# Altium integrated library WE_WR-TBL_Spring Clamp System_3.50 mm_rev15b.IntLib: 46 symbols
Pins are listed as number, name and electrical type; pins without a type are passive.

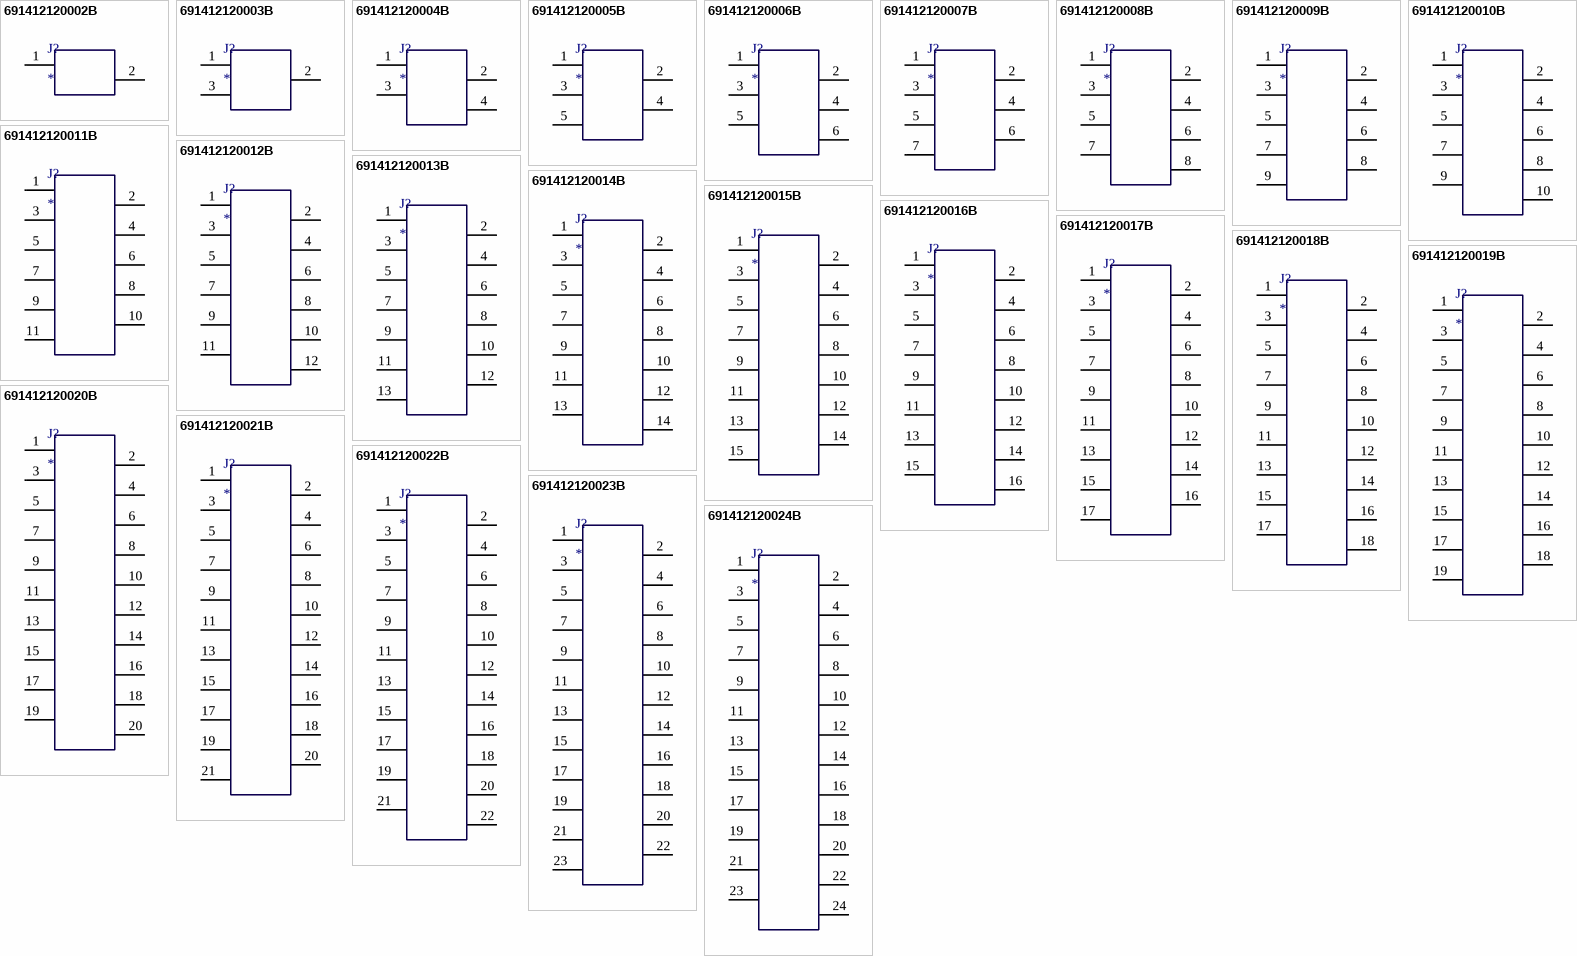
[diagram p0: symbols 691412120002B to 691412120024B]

## 691412120002B
designator J?
WR-TBL Screwless Entry 45° Grey,Serie 412 B - 3.50 mm; Manufacturer: Würth Elektronik eiSos GmbH; partNo: 691412120002B; ComponentLink1 Description: Manufacturer; ComponentLink2 Description: Datasheet; NoPins: 2
footprint 691412120002B
pins: 1, 2

## 691412120003B
designator J?
WR-TBL Screwless Entry 45° Grey,Serie 412 B - 3.50 mm; Manufacturer: Würth Elektronik eiSos GmbH; partNo: 691412120003B; ComponentLink1 Description: Manufacturer; ComponentLink2 Description: Datasheet; NoPins: 3
footprint 691412120003B
pins: 1, 2, 3

## 691412120004B
designator J?
WR-TBL Screwless Entry 45° Grey,Serie 412 B - 3.50 mm; Manufacturer: Würth Elektronik eiSos GmbH; partNo: 691412120004B; ComponentLink1 Description: Manufacturer; ComponentLink2 Description: Datasheet; NoPins: 4
footprint 691412120004B
pins: 1, 2, 3, 4

## 691412120005B
designator J?
WR-TBL Screwless Entry 45° Grey,Serie 412 B - 3.50 mm; Manufacturer: Würth Elektronik eiSos GmbH; partNo: 691412120005B; ComponentLink1 Description: Manufacturer; ComponentLink2 Description: Datasheet; NoPins: 5
footprint 691412120005B
pins: 1, 2, 3, 4, 5

## 691412120006B
designator J?
WR-TBL Screwless Entry 45° Grey,Serie 412 B - 3.50 mm; Manufacturer: Würth Elektronik eiSos GmbH; partNo: 691412120006B; ComponentLink1 Description: Manufacturer; ComponentLink2 Description: Datasheet; NoPins: 6
footprint 691412120006B
pins: 1, 2, 3, 4, 5, 6

## 691412120007B
designator J?
WR-TBL Screwless Entry 45° Grey,Serie 412 B - 3.50 mm; Manufacturer: Würth Elektronik eiSos GmbH; partNo: 691412120007B; ComponentLink1 Description: Manufacturer; ComponentLink2 Description: Datasheet; NoPins: 7
footprint 691412120007B
pins: 1, 2, 3, 4, 5, 6, 7

## 691412120008B
designator J?
WR-TBL Screwless Entry 45° Grey,Serie 412 B - 3.50 mm; Manufacturer: Würth Elektronik eiSos GmbH; partNo: 691412120008B; ComponentLink1 Description: Manufacturer; ComponentLink2 Description: Datasheet; NoPins: 8
footprint 691412120008B
pins: 1, 2, 3, 4, 5, 6, 7, 8

## 691412120009B
designator J?
WR-TBL Screwless Entry 45° Grey,Serie 412 B - 3.50 mm; Manufacturer: Würth Elektronik eiSos GmbH; partNo: 691412120009B; ComponentLink1 Description: Manufacturer; ComponentLink2 Description: Datasheet; NoPins: 9
footprint 691412120009B
pins: 1, 2, 3, 4, 5, 6, 7, 8, 9

## 691412120010B
designator J?
WR-TBL Screwless Entry 45° Grey,Serie 412 B - 3.50 mm; Manufacturer: Würth Elektronik eiSos GmbH; partNo: 691412120010B; ComponentLink1 Description: Manufacturer; ComponentLink2 Description: Datasheet; NoPins: 10
footprint 691412120010B
pins: 1, 2, 3, 4, 5, 6, 7, 8, 9, 10

## 691412120011B
designator J?
WR-TBL Screwless Entry 45° Grey,Serie 412 B - 3.50 mm; Manufacturer: Würth Elektronik eiSos GmbH; partNo: 691412120011B; ComponentLink1 Description: Manufacturer; ComponentLink2 Description: Datasheet; NoPins: 11
footprint 691412120011B
pins: 1, 2, 3, 4, 5, 6, 7, 8, 9, 10, 11

## 691412120012B
designator J?
WR-TBL Screwless Entry 45° Grey,Serie 412 B - 3.50 mm; Manufacturer: Würth Elektronik eiSos GmbH; partNo: 691412120012B; ComponentLink1 Description: Manufacturer; ComponentLink2 Description: Datasheet; NoPins: 12
footprint 691412120012B
pins: 1, 2, 3, 4, 5, 6, 7, 8, 9, 10, 11, 12

## 691412120013B
designator J?
WR-TBL Screwless Entry 45° Grey,Serie 412 B - 3.50 mm; Manufacturer: Würth Elektronik eiSos GmbH; partNo: 691412120013B; ComponentLink1 Description: Manufacturer; ComponentLink2 Description: Datasheet; NoPins: 13
footprint 691412120013B
pins: 1, 2, 3, 4, 5, 6, 7, 8, 9, 10, 11, 12, 13

## 691412120014B
designator J?
WR-TBL Screwless Entry 45° Grey,Serie 412 B - 3.50 mm; Manufacturer: Würth Elektronik eiSos GmbH; partNo: 691412120014B; ComponentLink1 Description: Manufacturer; ComponentLink2 Description: Datasheet; NoPins: 14
footprint 691412120014B
pins: 1, 2, 3, 4, 5, 6, 7, 8, 9, 10, 11, 12, 13, 14

## 691412120015B
designator J?
WR-TBL Screwless Entry 45° Grey,Serie 412 B - 3.50 mm; Manufacturer: Würth Elektronik eiSos GmbH; partNo: 691412120015B; ComponentLink1 Description: Manufacturer; ComponentLink2 Description: Datasheet; NoPins: 15
footprint 691412120015B
pins: 1, 2, 3, 4, 5, 6, 7, 8, 9, 10, 11, 12, 13, 14, 15

## 691412120016B
designator J?
WR-TBL Screwless Entry 45° Grey,Serie 412 B - 3.50 mm; Manufacturer: Würth Elektronik eiSos GmbH; partNo: 691412120016B; ComponentLink1 Description: Manufacturer; ComponentLink2 Description: Datasheet; NoPins: 16
footprint 691412120016B
pins: 1, 2, 3, 4, 5, 6, 7, 8, 9, 10, 11, 12, 13, 14, 15, 16

## 691412120017B
designator J?
WR-TBL Screwless Entry 45° Grey,Serie 412 B - 3.50 mm; Manufacturer: Würth Elektronik eiSos GmbH; partNo: 691412120017B; ComponentLink1 Description: Manufacturer; ComponentLink2 Description: Datasheet; NoPins: 17
footprint 691412120017B
pins: 1, 2, 3, 4, 5, 6, 7, 8, 9, 10, 11, 12, 13, 14, 15, 16, 17

## 691412120018B
designator J?
WR-TBL Screwless Entry 45° Grey,Serie 412 B - 3.50 mm; Manufacturer: Würth Elektronik eiSos GmbH; partNo: 691412120018B; ComponentLink1 Description: Manufacturer; ComponentLink2 Description: Datasheet; NoPins: 18
footprint 691412120018B
pins: 1, 2, 3, 4, 5, 6, 7, 8, 9, 10, 11, 12, 13, 14, 15, 16, 17, 18

## 691412120019B
designator J?
WR-TBL Screwless Entry 45° Grey,Serie 412 B - 3.50 mm; Manufacturer: Würth Elektronik eiSos GmbH; partNo: 691412120019B; ComponentLink1 Description: Manufacturer; ComponentLink2 Description: Datasheet; NoPins: 19
footprint 691412120019B
pins: 1, 2, 3, 4, 5, 6, 7, 8, 9, 10, 11, 12, 13, 14, 15, 16, 17, 18, 19

## 691412120020B
designator J?
WR-TBL Screwless Entry 45° Grey,Serie 412 B - 3.50 mm; Manufacturer: Würth Elektronik eiSos GmbH; partNo: 691412120020B; ComponentLink1 Description: Manufacturer; ComponentLink2 Description: Datasheet; NoPins: 20
footprint 691412120020B
pins: 1, 2, 3, 4, 5, 6, 7, 8, 9, 10, 11, 12, 13, 14, 15, 16, 17, 18, 19, 20

## 691412120021B
designator J?
WR-TBL Screwless Entry 45° Grey,Serie 412 B - 3.50 mm; Manufacturer: Würth Elektronik eiSos GmbH; partNo: 691412120021B; ComponentLink1 Description: Manufacturer; ComponentLink2 Description: Datasheet; NoPins: 21
footprint 691412120021B
pins: 1, 2, 3, 4, 5, 6, 7, 8, 9, 10, 11, 12, 13, 14, 15, 16, 17, 18, 19, 20, 21

## 691412120022B
designator J?
WR-TBL Screwless Entry 45° Grey,Serie 412 B - 3.50 mm; Manufacturer: Würth Elektronik eiSos GmbH; partNo: 691412120022B; ComponentLink1 Description: Manufacturer; ComponentLink2 Description: Datasheet; NoPins: 22
footprint 691412120022B
pins: 1, 2, 3, 4, 5, 6, 7, 8, 9, 10, 11, 12, 13, 14, 15, 16, 17, 18, 19, 20, 21, 22

## 691412120023B
designator J?
WR-TBL Screwless Entry 45° Grey,Serie 412 B - 3.50 mm; Manufacturer: Würth Elektronik eiSos GmbH; partNo: 691412120023B; ComponentLink1 Description: Manufacturer; ComponentLink2 Description: Datasheet; NoPins: 23
footprint 691412120023B
pins: 1, 2, 3, 4, 5, 6, 7, 8, 9, 10, 11, 12, 13, 14, 15, 16, 17, 18, 19, 20, 21, 22, 23

## 691412120024B
designator J?
WR-TBL Screwless Entry 45° Grey,Serie 412 B - 3.50 mm; Manufacturer: Würth Elektronik eiSos GmbH; partNo: 691412120024B; ComponentLink1 Description: Manufacturer; ComponentLink2 Description: Datasheet; NoPins: 24
footprint 691412120024B
pins: 1, 2, 3, 4, 5, 6, 7, 8, 9, 10, 11, 12, 13, 14, 15, 16, 17, 18, 19, 20, 21, 22, 23, 24


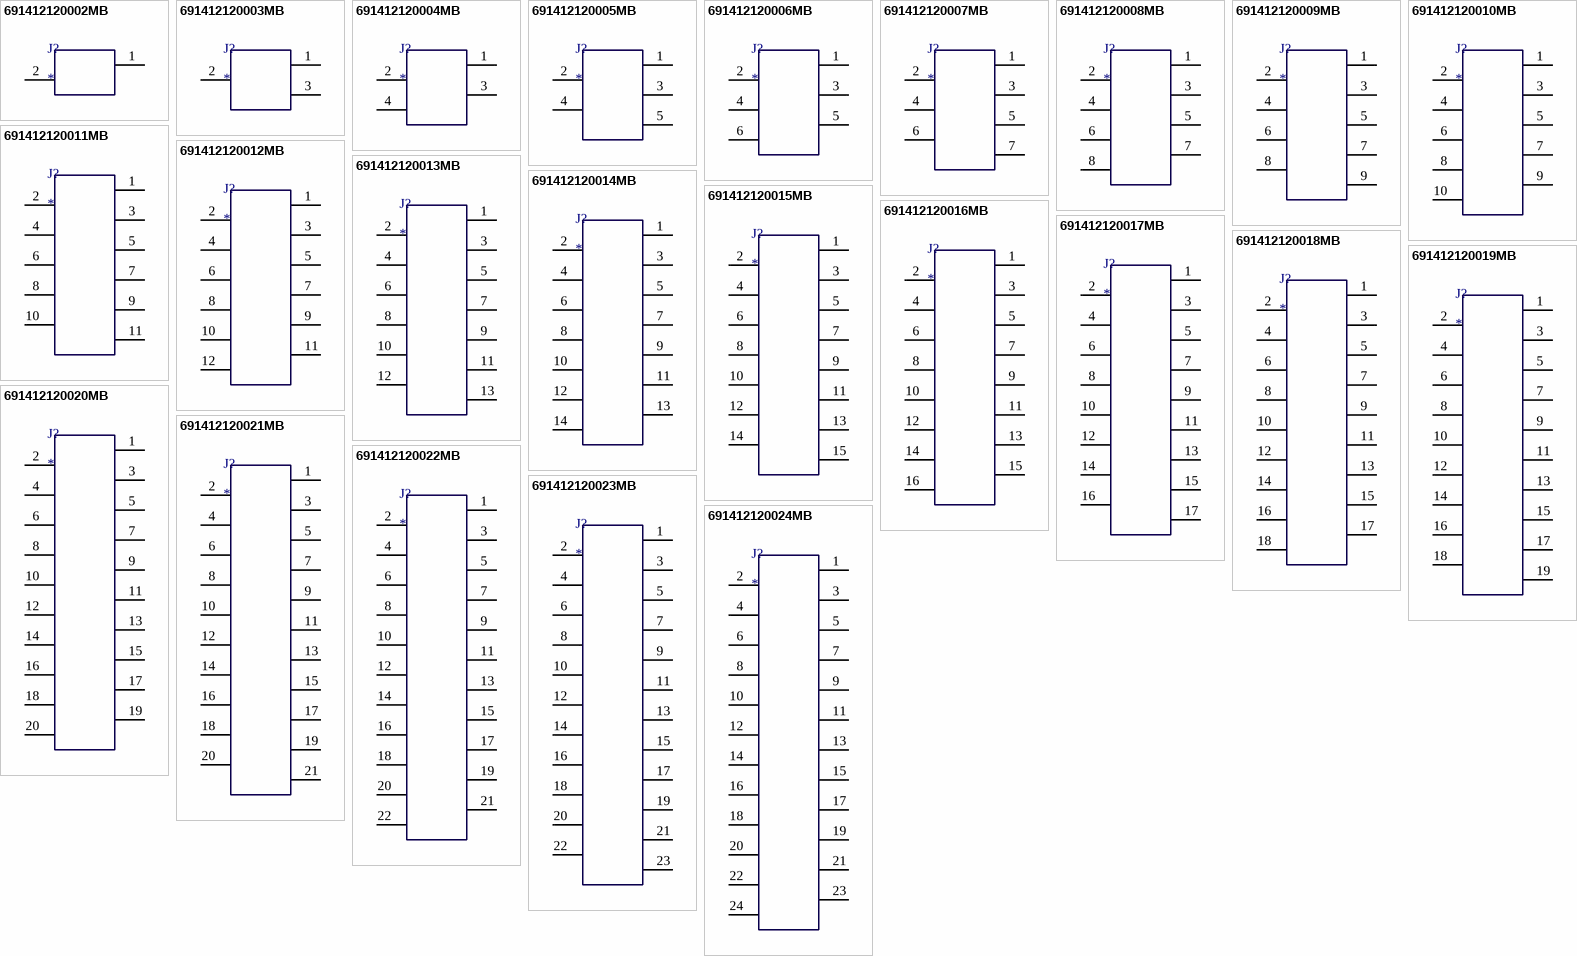
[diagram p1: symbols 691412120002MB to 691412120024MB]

## 691412120002MB
designator J?
WR-TBL Screwless Entry 45° Grey,Serie 412 MB - 3.50 mm; Manufacturer: Würth Elektronik eiSos GmbH; partNo: 691412120002MB; ComponentLink1 Description: Manufacturer; ComponentLink2 Description: Datasheet; NoPins: 2
footprint 691412120002MB
pins: 1, 2

## 691412120003MB
designator J?
WR-TBL Screwless Entry 45° Grey,Serie 412 MB - 3.50 mm; Manufacturer: Würth Elektronik eiSos GmbH; partNo: 691412120003MB; ComponentLink1 Description: Manufacturer; ComponentLink2 Description: Datasheet; NoPins: 3
footprint 691412120003MB
pins: 1, 2, 3

## 691412120004MB
designator J?
WR-TBL Screwless Entry 45° Grey,Serie 412 MB - 3.50 mm; Manufacturer: Würth Elektronik eiSos GmbH; partNo: 691412120004MB; ComponentLink1 Description: Manufacturer; ComponentLink2 Description: Datasheet; NoPins: 4
footprint 691412120004MB
pins: 1, 2, 3, 4

## 691412120005MB
designator J?
WR-TBL Screwless Entry 45° Grey,Serie 412 MB - 3.50 mm; Manufacturer: Würth Elektronik eiSos GmbH; partNo: 691412120005MB; ComponentLink1 Description: Manufacturer; ComponentLink2 Description: Datasheet; NoPins: 5
footprint 691412120005MB
pins: 1, 2, 3, 4, 5

## 691412120006MB
designator J?
WR-TBL Screwless Entry 45° Grey,Serie 412 MB - 3.50 mm; Manufacturer: Würth Elektronik eiSos GmbH; partNo: 691412120006MB; ComponentLink1 Description: Manufacturer; ComponentLink2 Description: Datasheet; NoPins: 6
footprint 691412120006MB
pins: 1, 2, 3, 4, 5, 6

## 691412120007MB
designator J?
WR-TBL Screwless Entry 45° Grey,Serie 412 MB - 3.50 mm; Manufacturer: Würth Elektronik eiSos GmbH; partNo: 691412120007MB; ComponentLink1 Description: Manufacturer; ComponentLink2 Description: Datasheet; NoPins: 7
footprint 691412120007MB
pins: 1, 2, 3, 4, 5, 6, 7

## 691412120008MB
designator J?
WR-TBL Screwless Entry 45° Grey,Serie 412 MB - 3.50 mm; Manufacturer: Würth Elektronik eiSos GmbH; partNo: 691412120008MB; ComponentLink1 Description: Manufacturer; ComponentLink2 Description: Datasheet; NoPins: 8
footprint 691412120008MB
pins: 1, 2, 3, 4, 5, 6, 7, 8

## 691412120009MB
designator J?
WR-TBL Screwless Entry 45° Grey,Serie 412 MB - 3.50 mm; Manufacturer: Würth Elektronik eiSos GmbH; partNo: 691412120009MB; ComponentLink1 Description: Manufacturer; ComponentLink2 Description: Datasheet; NoPins: 9
footprint 691412120009MB
pins: 1, 2, 3, 4, 5, 6, 7, 8, 9

## 691412120010MB
designator J?
WR-TBL Screwless Entry 45° Grey,Serie 412 MB - 3.50 mm; Manufacturer: Würth Elektronik eiSos GmbH; partNo: 691412120010MB; ComponentLink1 Description: Manufacturer; ComponentLink2 Description: Datasheet; NoPins: 10
footprint 691412120010MB
pins: 1, 2, 3, 4, 5, 6, 7, 8, 9, 10

## 691412120011MB
designator J?
WR-TBL Screwless Entry 45° Grey,Serie 412 MB - 3.50 mm; Manufacturer: Würth Elektronik eiSos GmbH; partNo: 691412120011MB; ComponentLink1 Description: Manufacturer; ComponentLink2 Description: Datasheet; NoPins: 11
footprint 691412120011MB
pins: 1, 2, 3, 4, 5, 6, 7, 8, 9, 10, 11

## 691412120012MB
designator J?
WR-TBL Screwless Entry 45° Grey,Serie 412 MB - 3.50 mm; Manufacturer: Würth Elektronik eiSos GmbH; partNo: 691412120012MB; ComponentLink1 Description: Manufacturer; ComponentLink2 Description: Datasheet; NoPins: 12
footprint 691412120012MB
pins: 1, 2, 3, 4, 5, 6, 7, 8, 9, 10, 11, 12

## 691412120013MB
designator J?
WR-TBL Screwless Entry 45° Grey,Serie 412 MB - 3.50 mm; Manufacturer: Würth Elektronik eiSos GmbH; partNo: 691412120013MB; ComponentLink1 Description: Manufacturer; ComponentLink2 Description: Datasheet; NoPins: 13
footprint 691412120013MB
pins: 1, 2, 3, 4, 5, 6, 7, 8, 9, 10, 11, 12, 13

## 691412120014MB
designator J?
WR-TBL Screwless Entry 45° Grey,Serie 412 MB - 3.50 mm; Manufacturer: Würth Elektronik eiSos GmbH; partNo: 691412120014MB; ComponentLink1 Description: Manufacturer; ComponentLink2 Description: Datasheet; NoPins: 14
footprint 691412120014MB
pins: 1, 2, 3, 4, 5, 6, 7, 8, 9, 10, 11, 12, 13, 14

## 691412120015MB
designator J?
WR-TBL Screwless Entry 45° Grey,Serie 412 MB - 3.50 mm; Manufacturer: Würth Elektronik eiSos GmbH; partNo: 691412120015MB; ComponentLink1 Description: Manufacturer; ComponentLink2 Description: Datasheet; NoPins: 15
footprint 691412120015MB
pins: 1, 2, 3, 4, 5, 6, 7, 8, 9, 10, 11, 12, 13, 14, 15

## 691412120016MB
designator J?
WR-TBL Screwless Entry 45° Grey,Serie 412 MB - 3.50 mm; Manufacturer: Würth Elektronik eiSos GmbH; partNo: 691412120016MB; ComponentLink1 Description: Manufacturer; ComponentLink2 Description: Datasheet; NoPins: 16
footprint 691412120016MB
pins: 1, 2, 3, 4, 5, 6, 7, 8, 9, 10, 11, 12, 13, 14, 15, 16

## 691412120017MB
designator J?
WR-TBL Screwless Entry 45° Grey,Serie 412 MB - 3.50 mm; Manufacturer: Würth Elektronik eiSos GmbH; partNo: 691412120017MB; ComponentLink1 Description: Manufacturer; ComponentLink2 Description: Datasheet; NoPins: 17
footprint 691412120017MB
pins: 1, 2, 3, 4, 5, 6, 7, 8, 9, 10, 11, 12, 13, 14, 15, 16, 17

## 691412120018MB
designator J?
WR-TBL Screwless Entry 45° Grey,Serie 412 MB - 3.50 mm; Manufacturer: Würth Elektronik eiSos GmbH; partNo: 691412120018MB; ComponentLink1 Description: Manufacturer; ComponentLink2 Description: Datasheet; NoPins: 18
footprint 691412120018MB
pins: 1, 2, 3, 4, 5, 6, 7, 8, 9, 10, 11, 12, 13, 14, 15, 16, 17, 18

## 691412120019MB
designator J?
WR-TBL Screwless Entry 45° Grey,Serie 412 MB - 3.50 mm; Manufacturer: Würth Elektronik eiSos GmbH; partNo: 691412120019MB; ComponentLink1 Description: Manufacturer; ComponentLink2 Description: Datasheet; NoPins: 19
footprint 691412120019MB
pins: 1, 2, 3, 4, 5, 6, 7, 8, 9, 10, 11, 12, 13, 14, 15, 16, 17, 18, 19

## 691412120020MB
designator J?
WR-TBL Screwless Entry 45° Grey,Serie 412 MB - 3.50 mm; Manufacturer: Würth Elektronik eiSos GmbH; partNo: 691412120020MB; ComponentLink1 Description: Manufacturer; ComponentLink2 Description: Datasheet; NoPins: 20
footprint 691412120020MB
pins: 1, 2, 3, 4, 5, 6, 7, 8, 9, 10, 11, 12, 13, 14, 15, 16, 17, 18, 19, 20

## 691412120021MB
designator J?
WR-TBL Screwless Entry 45° Grey,Serie 412 MB - 3.50 mm; Manufacturer: Würth Elektronik eiSos GmbH; partNo: 691412120021MB; ComponentLink1 Description: Manufacturer; ComponentLink2 Description: Datasheet; NoPins: 21
footprint 691412120021MB
pins: 1, 2, 3, 4, 5, 6, 7, 8, 9, 10, 11, 12, 13, 14, 15, 16, 17, 18, 19, 20, 21

## 691412120022MB
designator J?
WR-TBL Screwless Entry 45° Grey,Serie 412 MB - 3.50 mm; Manufacturer: Würth Elektronik eiSos GmbH; partNo: 691412120022MB; ComponentLink1 Description: Manufacturer; ComponentLink2 Description: Datasheet; NoPins: 22
footprint 691412120022MB
pins: 1, 2, 3, 4, 5, 6, 7, 8, 9, 10, 11, 12, 13, 14, 15, 16, 17, 18, 19, 20, 21, 22

## 691412120023MB
designator J?
WR-TBL Screwless Entry 45° Grey,Serie 412 MB - 3.50 mm; Manufacturer: Würth Elektronik eiSos GmbH; partNo: 691412120023MB; ComponentLink1 Description: Manufacturer; ComponentLink2 Description: Datasheet; NoPins: 23
footprint 691412120023MB
pins: 1, 2, 3, 4, 5, 6, 7, 8, 9, 10, 11, 12, 13, 14, 15, 16, 17, 18, 19, 20, 21, 22, 23

## 691412120024MB
designator J?
WR-TBL Screwless Entry 45° Grey,Serie 412 MB - 3.50 mm; Manufacturer: Würth Elektronik eiSos GmbH; partNo: 691412120024MB; ComponentLink1 Description: Manufacturer; ComponentLink2 Description: Datasheet; NoPins: 24
footprint 691412120024MB
pins: 1, 2, 3, 4, 5, 6, 7, 8, 9, 10, 11, 12, 13, 14, 15, 16, 17, 18, 19, 20, 21, 22, 23, 24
